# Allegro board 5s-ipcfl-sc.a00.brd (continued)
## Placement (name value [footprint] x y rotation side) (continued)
NOREF#25  -  [unnamed#2]  32.33 16.79 0 top
NOREF#26  -  []  60.38 238.12 0 top
NOREF#27  -  []  239.42 114.25 0 top
NOREF#28  -  []  112.34 232.56 0 top
NOREF#29  -  []  27.81 225.63 90 top
NOREF#30  -  []  7.34 241.53 0 top
NOREF#31  -  []  40.71 51.48 0 top
NOREF#32  -  []  31.98 208.58 0 top
NOREF#33  -  []  241.99 175.21 90 top
NOREF#34  -  []  62.43 110.49 0 top
NOREF#35  -  []  22.07 96.17 90 top
NOREF#36  -  []  206.78 1.97 0 top
NOREF#37  -  [unnamed#2]  17.88 237.82 0 top
NOREF#38  -  []  241.4 210.33 90 top
NOREF#39  -  []  109.69 88.81 0 top
NOREF#40  -  []  101.56 88.81 0 top
NOREF#41  -  []  241 46.07 90 top
NOREF#42  -  []  83.02 88.81 0 top
NOREF#43  -  []  37.62 56.97 0 top
NOREF#44  -  []  6.48 119.45 0 top
NOREF#45  -  []  48.08 5.31 0 top
NOREF#46  -  []  158.57 89 0 top
NOREF#47  -  []  149.2 14.69 0 top
NOREF#48  -  []  96.22 39.9 0 top
NOREF#49  -  []  129.3 53.59 0 top
NOREF#50  -  []  129.95 230.68 0 top
NOREF#51  -  []  138.35 32.37 0 top
NOREF#52  -  [unnamed#2]  229.49 25.76 0 top
NOREF#53  -  []  16.77 155.88 0 top
NOREF#54  -  []  14.7 232.64 90 top
NOREF#55  -  []  194.73 239.53 0 top
NOREF#56  -  []  125.09 2.29 0 top
NOREF#57  -  []  80.42 13.59 0 top
NOREF#58  -  []  109.54 104.73 0 top
NOREF#59  -  []  123.85 44.65 0 top
NOREF#60  -  []  47.37 -43.4 0 top
NOREF#61  -  []  38.2 78.61 0 top
NOREF#62  -  []  146.81 2.16 0 top
NOREF#63  -  []  106.77 89.45 0 top
NOREF#64  -  []  241.27 10.77 90 top
NOREF#65  -  []  38.23 128.02 0 top
NOREF#66  -  []  165.89 210.38 0 top
NOREF#67  -  []  90.6 88.75 0 top
NOREF#68  -  []  36.6 13.84 0 top
NOREF#69  -  []  160.88 4.92 0 top
NOREF#70  -  [unnamed#2]  24.28 235.13 180 bottom
NOREF#71  -  [unnamed#2]  215.01 10.03 180 bottom
NOREF#72  -  [unnamed#2]  227.33 237.97 180 bottom
O2C1  2200PF/50V  [MX_C0402_SMALL_T01]  226.44 29.44 180 top
O2C2  100PF/50V  [MX_C0402_SMALL_T01]  66.98 71.17 0 top
O2C4  100PF/50V  [MX_C0402_SMALL_T01]  227.74 74.83 180 top
O2C5  2200PF/50V  [MX_C0402_SMALL_T01]  225.65 28.32 0 top
O2CB1  0.1UF/6.3V  [MX_C0201]  204.22 29.64 180 top
O2CB2  0.1UF/16V  [MX_C0402_SMALL_T01]  225.3 22.1 270 top
O2CB3  0.1UF/6.3V  [MX_C0201]  222.61 42.04 0 top
O2CB4  0.1UF/6.3V  [MX_C0201]  224.87 31.37 90 top
O2CB5  0.1UF/6.3V  [MX_C0201]  225.48 37.05 0 top
O2CB6  0.1UF/6.3V  [MX_C0201]  225.48 37.97 0 top
O2CB7  0.1UF/16V  [MX_C0402_SMALL_T01]  217.93 22.1 270 top
O2CB8  0.1UF/16V  [MX_C0402_SMALL_T01]  207.8 22.05 270 top
O2CB10  0.1UF/16V  [MX_C0402_SMALL_T01]  220.24 21.97 270 top
O2CB11  0.1UF/16V  [MX_C0402_SMALL_T01]  219.33 22.1 270 top
O2CB12  470PF/50V  [MX_C0402_SMALL_T01]  204.19 27.79 180 top
O2CB15  0.1UF/16V  [MX_C0402_SMALL_T01]  226.31 24.37 0 top
O2CB16  0.1UF/16V  [MX_C0402_SMALL_T01]  224.38 22.1 270 top
O2CB17  0.1UF/6.3V  [MX_C0201]  216.92 43.31 90 top
O2CB19  0.1UF/6.3V  [MX_C0201]  227.33 32.59 270 top
O2CB20  0.1UF/6.3V  [MX_C0201]  225.78 31.37 90 top
O2Q6  MBT3904DW1T1G  [MX_SOT363_PHILIPS]  219.58 46.1 90 top
O2R1  43.2  [MX_R0402_SMALL_T01]  222.07 21.97 90 top
O2R2  3K  [MX_R0402_SMALL_T01]  228.24 32.59 270 top
O2R3  8.2K  [MX_R0402_SMALL_T01]  216.81 48.06 180 top
O2R5  10K  [MX_R0402_SMALL_T01]  225.54 36.12 180 top
O2R8  680  [MX_R0402_SMALL_T01]  218.44 48.06 0 top
O2R10  330K  [MX_R0402_SMALL_T01]  226.31 23.44 180 top
O2R11  30K  [MX_R0402_SMALL_T01]  220.34 47.88 0 top
O2R20  10K  [MX_R0402_SMALL_T01]  217.86 43.31 270 top
O2R21  30K  [MX_R0402_SMALL_T01]  206.25 45.85 270 top
O2R22  2.74K  [MX_R0402_SMALL_T01]  228.75 33.86 180 top
O3R5  33  [MX_R0402_SMALL_T01]  59.87 10.64 0 top
OR3  1K  [MX_R0402_SMALL_T01]  223.44 21.97 90 top
OR5  20K  [MX_R0402_SMALL_T01]  215.26 19.51 180 top
OR6  8.45K  [TX_R0402]  215.26 20.42 180 top
OR22  10K  [MX_R0402_SMALL_T01]  204.22 30.94 180 top
OR29  10K  [MX_R0402_SMALL_T01]  202.51 25.12 0 top
OR34  1K  [MX_R0402_SMALL_T01]  204.22 26.87 0 top
OR35  10K  [MX_R0402_SMALL_T01]  204.2 34.39 180 top
OR37  10K  [MX_R0402_SMALL_T01]  216.81 45.55 90 top
OR44  10K  [MX_R0402_SMALL_T01]  204.17 25.96 180 top
OR51  10K  [MX_R0402_SMALL_T01]  207.8 53.75 180 top
OR52  1K  [MX_R0402_SMALL_T01]  207.77 49.15 90 top
OR53  10K  [MX_R0402_SMALL_T01]  212.29 43.31 90 top
OR56  10K  [MX_R0402_SMALL_T01]  220.62 43.29 270 top
OR57  10K  [MX_R0402_SMALL_T01]  218.8 43.29 270 top
OR59  10K  [MX_R0402_SMALL_T01]  227.15 35.23 180 top
OR60  0  [MX_R0402_SMALL_T01]  213.23 43.31 270 top
OR61  0  [MX_R0402_SMALL_T01]  215.06 43.31 270 top
OR65  1K  [MX_R0402_SMALL_T01]  207.77 47.5 270 top
OR68  8.2K  [MX_R0402_SMALL_T01]  213.16 49.43 90 top
OR69  8.2K  [MX_R0402_SMALL_T01]  211.81 49 180 top
OR70  10K  [MX_R0402_SMALL_T01]  204.7 7.37 0 top
P1C2  470PF/50V  [MX_C0402_SMALL_T01]  235.08 148.21 180 top
P1CB1  0.1UF/16V  [MX_C0402_SMALL_T01]  229.87 194.18 180 top
P1CB2  0.1UF/6.3V  [MX_C0201]  229.34 186.31 270 top
P1CB3  0.1UF/6.3V  [MX_C0201]  229.87 201.04 180 top
P1CB4  0.1UF/6.3V  [MX_C0201]  229.67 151.23 180 top
P1CB5  1UF/6.3V  [MX_C0402_SMALL_T01]  230.2 163.09 90 top
P1CB8  0.1UF/16V  [MX_C0402_SMALL_T01]  229.67 150.32 180 top
P1CB10  1000PF/50V  [MX_C0402_SMALL_T01]  62.74 218.95 0 top
P1CB11  1000PF/50V  [MX_C0402_SMALL_T01]  62.74 219.96 0 top
P1CB12  0.1UF/16V  [MX_C0402_SMALL_T01]  230.2 166.24 270 top
P1CB13  10UF/25V  [MX_C1206_H75]  49.86 201.5 0 top
P1CB14  10UF/25V  [MX_C1206_H75]  51.18 163.47 0 top
P1CB15  10UF/25V  [MX_C1206_H75]  51.18 160.93 0 top
P1CB16  10UF/25V  [MX_C1206_H75]  49.94 182.68 0 top
P1CB17  10PF/50V  [MX_C0402_SMALL_T01]  62.74 217.98 0 top
P1R1  8.2K  [MX_R0402_SMALL_T01]  230.25 168.28 90 top
P1R2  49.9  [MX_R0402_SMALL_T01]  235.08 146.18 180 top
P1R3  20K  [MX_R0402_SMALL_T01]  235.08 147.19 0 top
P1R4  100  [MX_R0402_SMALL_T01]  230.25 169.93 270 top
P3  POWER_CON_2X2P  [MX_PWR_2X2P_165_HD_LF3]  59.31 227.46 270 top
P7  AC_1205G  [MX_BUZZ_256_BD472_H394_LF3]  29.84 49.68 90 top
P17  HEADER_1X3P  [MX_HD_1X3P_100_LF3]  206.71 5.28 180 top
P23  HEADER_2X5P_K8  [MX_HD_2X5P_100_K8_LF3]  32.89 4.32 180 top
P24  BOX_HD_2X10P  [MX_BOX_HD_2X10P_79_K20_LF3]  238.12 101.09 270 top
P29  WAFER_HD_1X4P  [MX_WF_HD_1X4P_1H_LF3]  238.27 222.07 270 top
P61  SATA_CON_7P  [MX_SATA_CON_7P_50_2HD_LF3]  236.73 63.63 90 top
P62  SATA_CON_7P  [MX_SATA_CON_7P_50_2HD_LF3]  236.73 45.85 90 top
P63  SATA_CON_7P  [MX_SATA_CON_7P_50_2HD_LF3]  236.73 28.07 90 top
P64  SATA_CON_7P  [MX_SATA_CON_7P_50_2HD_LF3]  236.73 10.29 90 top
P70  WAFER_HD_4P  [MX_WF_HD_1X4P_100_HD_LF3]  151.26 238.38 0 top
P118  FPC_CON_12P  [MX_FPC_12P_20_2HD_ACES_B]  195.45 6.35 0 top
P150  BOX_HEAD_2X10P  [MX_BOX_HD_2X10P_79_K20_LF5]  238.12 127.15 270 top
P189  WAFER_HD_1X12P  [MX_WAFER_HD_1X12P_79_HD_LF5]  66.49 5.82 180 top
P215  HEADER_1X2P  [MX_HD_1X2P_100_LF3]  121.03 4.83 180 top
P216  HEADER_1X2P  [MX_HD_1X2P_100_LF3]  127.33 4.84 180 top
P217  HEADER_1X3P  [MX_HD_1X3P_100_LF3]  135 4.83 180 top
P311  HEADER_1X5P  [HD_1X5P_100_JVE_LF3]  146.65 4.83 180 top
P312  HEADER_1X4P  [HD_1X4P_79_LF3]  148.73 8.74 180 top
P458  WAFER_HD_4P  [MX_WF_HD_1X4P_100_HD_LF3]  132.97 238.38 0 top
P461  WAFER_HD_1X4P  [MX_WF_HD_1X4P_1H_LF3]  120.78 238.38 0 top
P_HDDFAN  WTOB_CON_4P  [MX_WTOB_4P_49_2H_XINA]  88.6 7.29 0 top
PC1  22UF/6.3V  [MX_C0603_SMALL_T02]  124.46 160.53 90 bottom
PC2  22UF/6.3V  [MX_C0603_SMALL_T02]  121.41 160.55 90 bottom
PC3  22UF/6.3V  [MX_C0603_SMALL_T02]  119.71 156.82 270 bottom
PC4  22UF/6.3V  [MX_C0603_SMALL_T02]  120.14 166.88 0 top
PC5  22UF/6.3V  [MX_C0603_SMALL_T02]  126.75 160.53 90 bottom
PC6  22UF/6.3V  [MX_C0603_SMALL_T02]  121.03 156.82 270 bottom
PC7  22UF/6.3V  [MX_C0603_SMALL_T02]  125.46 168.3 0 bottom
PC8  22UF/6.3V  [MX_C0603_SMALL_T02]  125.46 169.67 0 bottom
PC9  22UF/6.3V  [MX_C0603_SMALL_T02]  122.8 171.07 180 bottom
PC10  22UF/6.3V  [MX_C0603_SMALL_T02]  122.83 166.95 180 top
PC11  22UF/6.3V  [MX_C0603_SMALL_T02]  125.46 171.07 0 bottom
PC12  22UF/6.3V  [MX_C0603_SMALL_T02]  122.8 169.67 180 bottom
PC13  0.1UF/6.3V  [MX_C0201]  55.32 121.67 270 top
PC15  2.2UF/6.3V  [MX_C0603_SMALL_T01]  123.32 97.28 180 top
PC118  10UF/16V  [MX_C0805_SMALL_T02]  210.69 128.4 180 top
PC121  1000PF/50V  [MX_C0402_SMALL_T01]  52.27 123.7 180 top
PC122  22PF/50V  [MX_C0402_SMALL_T01]  213.23 128.55 0 top
PC126  330PF/50V  [MX_C0402_SMALL_T01]  214.45 124.84 0 top
PC131  1UF/25V  [MX_C0603_SMALL_T01]  214.04 133.13 0 top
PC132  1UF/25V  [MX_C0603_SMALL_T01]  238.9 211.48 180 top
PC133  1000PF/50V  [MX_C0402_SMALL_T01]  135.86 109.52 270 top
PC137  10UF/25V  [MX_C1206_H75]  66.14 129.06 90 top
PC138  10UF/25V  [MX_C1206_H75]  65.99 134.11 270 top
PC142  22UF/6.3V  [MX_C0603_SMALL_T02]  79.04 135.61 90 top
PC149  22UF/6.3V  [MX_C0603_SMALL_T02]  128.19 151.89 0 top
PC150  10UF/6.3V  [MX_C0603_SMALL_T01]  133.99 101.6 270 top
PC151  1UF/25V  [MX_C0603_SMALL_T01]  128.52 98.93 180 top
PC152  1000PF/50V  [MX_C0402_SMALL_T01]  135.1 96.01 90 top
PC153  0.022UF/16V  [MX_C0402_SMALL_T01]  125.09 103.12 270 top
PC154  0.033U/16V  [MX_C0402_SMALL_T01]  129.92 95.63 0 top
PC155  470PF/50V  [MX_C0402_SMALL_T01]  131.32 98.93 0 top
PC156  22UF/6.3V  [MX_C0603_SMALL_T02]  122.81 100.84 270 top
PC157  22UF/6.3V  [MX_C0603_SMALL_T02]  121.41 100.84 270 top
PC158  0.01UF/50V  [MX_C0402_SMALL_T01]  131.83 97.66 90 top
PC159  2200PF/50V  [MX_C0402_SMALL_T01]  131.7 100.33 270 top
PC160  4700PF/50V  [MX_C0402_SMALL_T01]  125.12 99.31 270 top
PC161  22UF/6.3V  [MX_C0603_SMALL_T02]  126.11 108.41 0 top
PC162  22UF/6.3V  [MX_C0603_SMALL_T02]  126.11 109.73 0 top
PC163  22UF/6.3V  [MX_C0603_SMALL_T02]  121.41 152.4 90 top
PC164  22UF/6.3V  [MX_C0603_SMALL_T02]  122.81 152.4 90 top
PC193  22UF/6.3V  [MX_C0603_SMALL_T02]  210.03 112.34 180 top
PC194  22UF/6.3V  [MX_C0603_SMALL_T02]  214.17 111.89 270 top
PC205  10UF/25V  [MX_C1206]  201.93 94.79 0 top
PC206  10UF/25V  [MX_C1206]  201.93 92.35 0 top
PC207  10UF/16V  [MX_C0805_SMALL_T02]  200.79 90.17 180 top
PC208  0.1UF/25V  [MX_C0603_SMALL_T01]  220.5 111.56 0 top
PC209  1000PF/50V  [MX_C0402_SMALL_T01]  189.43 91.47 180 top
PC210  0.1UF/25V  [MX_C0603_SMALL_T01]  195.91 92.02 90 top
PC211  1000PF/50V  [MX_C0402_SMALL_T01]  206.45 89.33 270 top
PC212  1UF/25V  [MX_C0603_SMALL_T01]  195.71 90.17 0 top
PC213  10UF/6.3V  [MX_C0603_SMALL_T01]  202.49 65.3 0 top
PC214  680PF/50V  [MX_C0603]  207.14 86.61 270 top
PC215  1000PF/50V  [MX_C0402_SMALL_T01]  202.44 82.55 0 top
PC217  56PF/50V  [MX_C0402_SMALL_T01]  189.18 89.64 0 top
PC218  0.1UF/25V  [MX_C0603_SMALL_T01]  187.43 90.81 90 top
PC231  0.1UF/6.3V  [MX_C0201]  230.17 160.53 270 top
PC232  1UF/25V  [MX_C0603_SMALL_T01]  227.97 165.61 0 top
PC233  1UF/25V  [MX_C0603_SMALL_T01]  228.35 190.25 180 top
PC234  0.1UF/6.3V  [MX_C0201]  226.19 195.58 180 top
PC236  1UF/25V  [MX_C0603_SMALL_T01]  226.06 190.25 180 top
PC238  0.1UF/6.3V  [MX_C0201]  230.25 186.31 270 top
PC239  22UF/6.3V  [MX_C0603_SMALL_T02]  224.92 165.61 180 top
PC240  22UF/6.3V  [MX_C0603_SMALL_T02]  224.92 164.21 180 top
PC241  0.1UF/16V  [MX_C0402_SMALL_T01]  229.74 184.53 0 top
PC242  1000PF/50V  [MX_C0402_SMALL_T01]  234.19 203.48 270 top
PC243  10UF/16V  [MX_C0805_SMALL_T02]  236.91 205.71 180 top
PC247  10PF/50V  [MX_C0402_SMALL_T01]  228.09 163.58 0 top
PC272  22UF/6.3V  [MX_C0603_SMALL_T02]  129.84 116.56 90 top
PC273  22UF/6.3V  [MX_C0603_SMALL_T02]  131.47 113.8 90 top
PC274  1UF/25V  [MX_C0603_SMALL_T01]  123.67 116.94 180 top
PC329  22UF/6.3V  [MX_C0603_SMALL_T02]  124.66 153.29 180 top
PC331  22UF/6.3V  [MX_C0603_SMALL_T02]  124.66 151.89 180 top
PC332  22UF/6.3V  [MX_C0603_SMALL_T02]  124.69 154.58 180 bottom
PC333  22UF/6.3V  [MX_C0603_SMALL_T02]  124.69 155.98 180 bottom
PC334  22UF/6.3V  [MX_C0603_SMALL_T02]  128.27 155.32 0 bottom
PC335  22UF/6.3V  [MX_C0603_SMALL_T02]  128.19 152.91 0 bottom
PC339  1000PF/50V  [MX_C0402_SMALL_T01]  217.67 145.34 180 top
PC341  10UF/16V  [MX_C0805_SMALL_T02]  217.68 136.12 180 top
PC343  1800PF/50V  [MX_C0402_SMALL_T01]  205.1 85.09 180 top
PC481  22UF/6.3V  [MX_C0603_SMALL_T02]  190.8 164.01 270 top
PC483  10UF/6.3V  [MX_C0603_SMALL]  212.85 156.16 0 top
PC484  1UF/6.3V  [MX_C0402_SMALL_T01]  207.82 145.19 180 top
PC485  1000PF/50V  [MX_C0402_SMALL_T01]  209.14 155.07 90 top
PC486  0.1UF/16V  [MX_C0402_SMALL_T01]  218.29 157.58 90 top
PC566  1000PF/50V  [MX_C0402_SMALL_T01]  120.02 56.13 90 top
PC567  1000PF/50V  [MX_C0402_SMALL_T01]  115.23 53.08 180 top
PC568  2.2UF/6.3V  [MX_C0603_SMALL_T01]  116.28 49.66 180 top
PC569  0.1UF/6.3V  [MX_C0201]  116.31 56.13 90 top
PC570  0.1UF/6.3V  [MX_C0201]  117.25 56.13 90 top
PC601  680PF/50V  [MX_C0402_SMALL_T01]  65.75 165.48 90 top
PC602  1000PF/50V  [MX_C0402_SMALL_T01]  65.61 154.28 180 top
PC603  1000PF/50V  [MX_C0402_SMALL_T01]  63.92 165.48 270 top
PC604  1000PF/50V  [MX_C0402_SMALL_T01]  64.85 155.97 270 top
PC605  1000PF/50V  [MX_C0402_SMALL_T01]  59.05 155.96 270 top
PC606  22UF/6.3V  [MX_C0603_SMALL_T02]  73.86 156.08 180 top
PC607  0.1UF/25V  [MX_C0603_SMALL_T01]  71.25 166.24 180 top
PC608  1UF/25V  [MX_C0603_SMALL_T01]  68.33 169.95 270 top
PC609  680PF/50V  [MX_C0402_SMALL_T01]  65.71 147.68 90 top
PC610  1000PF/50V  [MX_C0402_SMALL_T01]  65.89 136.93 180 top
PC611  1000PF/50V  [MX_C0402_SMALL_T01]  63.88 147.68 270 top
PC612  1000PF/50V  [MX_C0402_SMALL_T01]  59.05 138.28 270 top
PC613  1000PF/50V  [MX_C0402_SMALL_T01]  64.67 138.29 270 top
PC614  22UF/6.3V  [MX_C0603_SMALL_T02]  78.74 140.34 270 top
PC615  0.1UF/25V  [MX_C0603_SMALL_T01]  72.19 149.53 180 top
PC616  1UF/25V  [MX_C0603_SMALL_T01]  68.83 152.3 270 top
PC617  10UF/25V  [MX_C1206_H75]  51.18 153.62 0 top
PC618  10UF/25V  [MX_C1206_H75]  51.18 156.06 0 top
PC619  10UF/25V  [MX_C1206_H75]  50.62 170.54 0 top
PC620  10UF/25V  [MX_C1206_H75]  50.62 168.07 0 top
PC642  1UF/6.3V  [MX_C0402_SMALL_T01]  46.15 237.06 90 top
PC661  1NF/25V  [MX_C0402_SMALL_T01]  213.36 132.05 180 top
PC832  22UF/6.3V  [MX_C0603_SMALL_T02]  210.03 111 180 top
PC834  22UF/6.3V  [MX_C0603_SMALL_T02]  131.19 165.1 90 top
PC5801  0.1UF/6.3V  [MX_C0201]  72.64 209.3 270 top
PC5802  0.47UF/16V  [MX_C0603_SMALL_T01]  73.28 211.71 180 top
PC5803  0.47UF/16V  [MX_C0603_SMALL_T01]  75.31 211.63 270 top
PC5804  0.1UF/6.3V  [MX_C0201]  76.07 208.66 270 top
PC5805  0.47UF/16V  [MX_C0603_SMALL_T01]  72.97 214.83 180 top
PC5806  0.1UF/6.3V  [MX_C0201]  70.82 213.49 180 top
PC5807  0.47UF/16V  [MX_C0603_SMALL_T01]  76.9 225.68 90 top
PC5808  0.1UF/6.3V  [MX_C0201]  75.9 228.73 90 top
PC5809  0.47UF/16V  [MX_C0603_SMALL_T01]  78.27 225.68 90 top
PC5810  0.1UF/6.3V  [MX_C0201]  78.64 228.73 90 top
PC5811  0.47UF/16V  [MX_C0603_SMALL_T01]  78.36 211.68 270 top
PC5812  0.1UF/6.3V  [MX_C0201]  77.11 208.71 270 top
PC5813  0.1UF/16V  [MX_C0402_SMALL_T01]  73.15 218.44 180 top
PC5814  0.1UF/6.3V  [MX_C0201]  90.4 222.38 0 top
PC5815  1000PF/50V  [MX_C0402_SMALL_T01]  82.93 211.33 270 top
PC5816  82PF/50V  [MX_C0402_SMALL_T01]  80.52 213.36 0 top
PC5817  0.1UF/16V  [MX_C0402_SMALL_T01]  81.84 209.42 270 top
PC5818  270PF/50V  [MX_C0402_SMALL_T01]  80.01 209.42 90 top
PC5819  1000PF/50V  [MX_C0402_SMALL_T01]  82.55 212.85 0 top
PC5820  1000PF/50V  [MX_C0402_SMALL_T01]  83.12 226.06 90 top
PC5821  390PF/50V  [MX_C0402_SMALL_T01]  80.01 228.35 270 top
PC5822  0.1UF/16V  [MX_C0402_SMALL_T01]  81.92 228.78 90 top
PC5823  82PF/50V  [MX_C0402_SMALL_T01]  80.64 224.79 0 top
PC5824  1000PF/50V  [MX_C0402_SMALL_T01]  82.3 224.79 0 top
PC5825  0.1UF/16V  [MX_C0402_SMALL_T01]  70.94 217.17 0 top
PC5826  0.1UF/16V  [MX_C0402_SMALL_T01]  72.77 227.08 270 top
PC5827  0.47UF/25V  [MX_C0603_SMALL_T01]  88.85 220.07 0 top
PC5828  1000PF/50V  [MX_C0402_SMALL_T01]  86.36 225.58 0 top
PC5829  1UF/25V  [MX_C0603_SMALL_T01]  84.71 225.3 90 top
PC5830  0.1UF/16V  [MX_C0402_SMALL_T01]  72.77 221.74 180 top
PC5901  0.1UF/25V  [MX_C0603_SMALL_T01]  71.63 183.67 180 top
PC5902  1000PF/50V  [MX_C0402_SMALL_T01]  63.86 182.96 270 top
PC5903  1UF/25V  [MX_C0603_SMALL_T01]  69.09 188.95 180 top
PC5904  22UF/6.3V  [MX_C0603_SMALL_T02]  73.91 173.69 180 top
PC5905  680PF/50V  [MX_C0402_SMALL_T01]  65.68 182.96 90 top
PC5906  1000PF/50V  [MX_C0402_SMALL_T01]  65.53 171.96 180 top
PC5907  1000PF/50V  [MX_C0402_SMALL_T01]  59.05 173.48 270 top
PC5908  1000PF/50V  [MX_C0402_SMALL_T01]  64.77 173.53 270 top
PC5909  680PF/50V  [MX_C0402_SMALL_T01]  65.66 200.53 90 top
PC5910  1000PF/50V  [MX_C0402_SMALL_T01]  65.56 189.43 180 top
PC5911  1000PF/50V  [MX_C0402_SMALL_T01]  63.83 200.53 270 top
PC5912  1000PF/50V  [MX_C0402_SMALL_T01]  59.44 191.13 270 top
PC5913  1000PF/50V  [MX_C0402_SMALL_T01]  65.66 191.13 270 top
PC5914  22UF/6.3V  [MX_C0603_SMALL_T02]  74.68 191.16 180 top
PC5915  0.1UF/25V  [MX_C0603_SMALL_T01]  67.31 202.06 180 top
PC5916  1UF/25V  [MX_C0603_SMALL_T01]  64.52 206.12 180 top
PC5917  10UF/25V  [MX_C1206_H75]  49.94 186.66 0 top
PC5918  10UF/25V  [MX_C1206_H75]  49.94 189.1 0 top
PC5919  10UF/25V  [MX_C1206_H75]  49.83 194.94 0 top
PC5920  10UF/25V  [MX_C1206_H75]  49.83 197.38 0 top
PC6101  680PF/50V  [MX_C0402_SMALL_T01]  113.92 224.41 90 top
PC6102  1000PF/50V  [MX_C0402_SMALL_T01]  115.06 224.41 90 top
PC6103  1000PF/50V  [MX_C0402_SMALL_T01]  120.14 218.41 180 top
PC6104  1000PF/50V  [MX_C0402_SMALL_T01]  108.33 227.46 90 top
PC6105  1000PF/50V  [MX_C0402_SMALL_T01]  103.38 227.08 0 top
PC6106  22UF/6.3V  [MX_C0603_SMALL_T02]  108.71 201.55 180 top
PC6107  0.1UF/25V  [MX_C0603_SMALL_T01]  98.55 228.73 270 top
PC6108  1UF/25V  [MX_C0603_SMALL_T01]  92.66 226.59 180 top
PC6109  680PF/50V  [MX_C0402_SMALL_T01]  135.13 224.28 90 top
PC6110  1000PF/50V  [MX_C0402_SMALL_T01]  136.19 224.28 90 top
PC6111  1000PF/50V  [MX_C0402_SMALL_T01]  141.6 218.44 180 top
PC6112  1000PF/50V  [MX_C0402_SMALL_T01]  123.95 227.08 0 top
PC6113  1000PF/50V  [MX_C0402_SMALL_T01]  129.79 227.46 90 top
PC6114  22UF/6.3V  [MX_C0603_SMALL_T02]  123.44 201.55 180 top
PC6115  0.1UF/25V  [MX_C0603_SMALL_T01]  149.48 226.42 180 top
PC6116  1UF/25V  [MX_C0603_SMALL_T01]  144.63 228.68 180 top
PC6117  10UF/25V  [MX_C1206_H75]  114.53 227.66 90 top
PC6118  10UF/25V  [MX_C1206_H75]  119.15 233.93 180 top
PC6119  10UF/25V  [MX_C1206_H75]  140.39 232.11 270 top
PC6120  10UF/25V  [MX_C1206_H75]  135.92 227.94 90 top
PC6201  22UF/6.3V  [MX_C0603_SMALL_T02]  125.6 161.93 270 top
PC6202  22UF/6.3V  [MX_C0603_SMALL_T02]  127 161.93 270 top
PC6203  22UF/6.3V  [MX_C0603_SMALL_T02]  125.6 159.13 90 top
PC6204  22UF/6.3V  [MX_C0603_SMALL_T02]  127 159.13 90 top
PC6205  22UF/6.3V  [MX_C0603_SMALL_T02]  125.6 165.1 90 top
PC6206  22UF/6.3V  [MX_C0603_SMALL_T02]  129.79 165.1 90 top
PC6207  22UF/6.3V  [MX_C0603_SMALL_T02]  120.14 168.28 0 top
PC6208  22UF/6.3V  [MX_C0603_SMALL_T02]  121.41 159.13 90 top
PC6209  22UF/6.3V  [MX_C0603_SMALL_T02]  122.81 165.1 90 top
PC6210  22UF/6.3V  [MX_C0603_SMALL_T02]  124.21 159.13 90 top
PC6211  22UF/6.3V  [MX_C0603_SMALL_T02]  120.02 159.13 90 top
PC6212  22UF/6.3V  [MX_C0603_SMALL_T02]  120.02 161.93 270 top
PC6213  22UF/6.3V  [MX_C0603_SMALL_T02]  131.19 161.93 270 top
PC6214  22UF/6.3V  [MX_C0603_SMALL_T02]  122.81 156.72 270 top
PC6215  22UF/6.3V  [MX_C0603_SMALL_T02]  121.41 156.72 270 top
PC6216  22UF/6.3V  [MX_C0603_SMALL_T02]  124.21 161.93 270 top
PC6217  22UF/6.3V  [MX_C0603_SMALL_T02]  120.02 156.72 270 top
PC6218  22UF/6.3V  [MX_C0603_SMALL_T02]  124.21 165.1 90 top
PC6219  22UF/6.3V  [MX_C0603_SMALL_T02]  128.4 165.1 90 top
PC6220  22UF/6.3V  [MX_C0603_SMALL_T02]  127 165.1 90 top
PC6221  22UF/6.3V  [MX_C0603_SMALL_T02]  99.44 214.25 180 top
PC6222  22UF/6.3V  [MX_C0603_SMALL_T02]  129.21 209.4 0 top
PC6223  22UF/6.3V  [MX_C0603_SMALL_T02]  100.97 201.55 180 top
PC6224  22UF/6.3V  [MX_C0603_SMALL_T02]  123.44 200.15 180 top
PC6225  22UF/6.3V  [MX_C0603_SMALL_T02]  128.13 171.07 180 top
PC6226  22UF/6.3V  [MX_C0603_SMALL_T02]  125.46 169.67 0 top
PC6227  2.2UF/6.3V  [MX_C0603_SMALL_T01]  128.13 169.67 180 top
PC6228  22UF/6.3V  [MX_C0603_SMALL_T02]  125.46 168.28 0 top
PC6229  22UF/6.3V  [MX_C0603_SMALL_T02]  125.46 171.07 0 top
PC6230  22UF/6.3V  [MX_C0603_SMALL_T02]  122.8 168.28 180 top
PC6231  22UF/6.3V  [MX_C0603_SMALL_T02]  128.13 168.28 180 top
PC6232  22UF/6.3V  [MX_C0603_SMALL_T02]  122.8 171.07 180 top
PC6233  22UF/6.3V  [MX_C0603_SMALL_T02]  100.97 200.15 180 top
PC6234  22UF/6.3V  [MX_C0603_SMALL_T02]  108.71 200.15 180 top
PC6235  22UF/6.3V  [MX_C0603_SMALL_T02]  130.79 169.67 0 top
PC6236  22UF/6.3V  [MX_C0603_SMALL_T02]  130.79 171.07 0 top
PC6237  22UF/6.3V  [MX_C0603_SMALL_T02]  96.77 159.77 270 top
PC6238  22UF/6.3V  [MX_C0603_SMALL_T02]  96.77 165.1 270 top
PC6239  22UF/6.3V  [MX_C0603_SMALL_T02]  96.77 179.2 270 top
PC6240  22UF/6.3V  [MX_C0603_SMALL_T02]  96.77 174.37 90 top
PC6241  22UF/6.3V  [MX_C0603_SMALL_T02]  116.2 201.55 180 top
PC6242  22UF/6.3V  [MX_C0603_SMALL_T02]  116.2 200.15 180 top
PC6243  22UF/6.3V  [MX_C0603_SMALL_T02]  130.79 168.25 0 top
PC6244  22UF/6.3V  [MX_C0603_SMALL_T02]  122.8 169.67 180 top
PC6501  10UF/25V  [MX_C1206_H75]  210.87 205.74 0 top
PC6502  10UF/25V  [MX_C1206_H75]  210.87 203.17 0 top
PC6521  22UF/6.3V  [MX_C0603_SMALL_T02]  212.57 160.73 270 top
PC6522  22UF/6.3V  [MX_C0603_SMALL_T02]  212.9 154.66 0 top
PC6523  22UF/6.3V  [MX_C0603_SMALL_T02]  171.07 183.77 135 top
PC6524  22UF/6.3V  [MX_C0603_SMALL_T02]  211.54 172.16 90 top
PC6525  22UF/6.3V  [MX_C0603_SMALL_T02]  207.52 179.07 0 top
PC6526  0.1UF/25V  [MX_C0603_SMALL_T01]  228.45 206.55 270 top
PC6527  0.1UF/25V  [MX_C0603_SMALL_T01]  219.07 227.33 90 top
PC6805  10UF/6.3V  [MX_C0603_SMALL_T01]  43.26 237.85 90 top
PC6807  10UF/6.3V  [MX_C0603_SMALL_T01]  41.91 227.2 270 top
PC6808  10UF/6.3V  [MX_C0603_SMALL_T01]  43.18 227.2 270 top
PC6809  1000PF/50V  [MX_C0402_SMALL_T01]  44.78 227.89 0 top
PC6810  1UF/6.3V  [MX_C0402_SMALL_T01]  41.71 236.65 180 top
PC640625  22UF/6.3V  [MX_C0603_SMALL_T02]  120.14 169.67 0 top
PC640626  22UF/6.3V  [MX_C0603_SMALL_T02]  129.79 159.13 90 top
PC640627  22UF/6.3V  [MX_C0603_SMALL_T02]  129.79 161.93 270 top
PC640628  22UF/6.3V  [MX_C0603_SMALL_T02]  131.19 159.13 90 top
PC640629  22UF/6.3V  [MX_C0603_SMALL_T02]  121.41 161.93 270 top
PC640630  22UF/6.3V  [MX_C0603_SMALL_T02]  96.77 169.93 90 top
PC640631  100uF/16V  [MX_CE_100U_16V_5X11_LFH]  226.44 169.42 270 top
PC640632  22UF/6.3V  [MX_C0603_SMALL_T02]  124.66 156.08 180 top
PC640633  22UF/6.3V  [MX_C0603_SMALL_T02]  124.66 154.69 180 top
PC640634  22UF/6.3V  [MX_C0603_SMALL_T02]  128.27 156.08 0 top
PC640635  22UF/6.3V  [MX_C0603_SMALL_T02]  128.27 154.69 0 top
PC640636  22UF/6.3V  [MX_C0603_SMALL_T02]  128.19 153.29 0 top
PC640637  2200PF/50V  [MX_C0402_SMALL_T01]  66.42 119.51 270 top
PC640639  1000PF/50V  [MX_C0402_SMALL_T01]  76.07 137.31 180 top
PC640641  1000PF/50V  [MX_C0402_SMALL_T01]  70.48 129.74 90 top
PC640644  1000PF/50V  [MX_C0402_SMALL_T01]  66.42 121.16 90 top
PC640645  1000PF/50V  [MX_C0402_SMALL_T01]  68.76 135.36 90 top
PC640646  680PF/50V  [MX_C0402_SMALL_T01]  73.28 135.89 90 top
PC640647  0.1UF/25V  [MX_C0603_SMALL_T01]  73.28 121.41 0 top
PC640648  100PF/50V  [MX_C0402_SMALL_T01]  66.67 125.48 90 top
PC640649  4.7UF/25V  [MX_C0805_SMALL_T02]  70.31 124.56 180 top
PC640651  1000PF/50V  [MX_C0402_SMALL_T01]  76.07 138.23 180 top
PC640653  2200PF/50V  [MX_C0402_SMALL_T01]  212.09 224.03 180 top
PC640656  1000PF/50V  [MX_C0402_SMALL_T01]  210.69 193.57 90 top
PC640658  1000PF/50V  [MX_C0402_SMALL_T01]  219.68 198.32 180 top
PC640660  1000PF/50V  [MX_C0402_SMALL_T01]  209.22 198.11 0 top
PC640661  1000PF/50V  [MX_C0402_SMALL_T01]  213.59 224.41 90 top
PC640662  680PF/50V  [MX_C0402_SMALL_T01]  219.41 187.55 90 top
PC640663  0.1UF/25V  [MX_C0603_SMALL_T01]  213.23 216.19 270 top
PC640664  100PF/50V  [MX_C0402_SMALL_T01]  217.3 223.9 0 top
PC640665  4.7UF/6.3V  [MX_C0603_SMALL_T01]  216.28 217.81 270 top
PC640667  1000PF/50V  [MX_C0402_SMALL_T01]  210.69 187.9 90 top
PC640671  0.1UF/25V  [MX_C0603_SMALL_T01]  215.65 224.54 90 top
PC640672  0.1UF/16V  [MX_C0402_SMALL_T01]  65.81 123.04 0 top
PC640674  0.1UF/25V  [MX_C0603_SMALL_T01]  62.74 125.35 90 top
PC640675  1000PF/50V  [MX_C0402_SMALL_T01]  39.5 230.89 90 top
PC640676  10UF/16V  [MX_C0805_SMALL_T02]  35.94 228.22 90 top
PC640679  1UF/25V  [MX_C0603_SMALL_T01]  53.75 125.68 180 top
PC640681  0.1UF/6.3V  [MX_C0201]  51.31 131.01 180 top
PC640682  1UF/25V  [MX_C0603_SMALL_T01]  19.18 152.02 180 top
PC640683  10PF/50V  [MX_C0402_SMALL_T01]  55.85 201.98 270 top
PC640684  10PF/50V  [MX_C0402_SMALL_T01]  71.04 189.1 0 top
PC640685  10PF/50V  [MX_C0402_SMALL_T01]  66.04 207.7 90 top
PC640686  10PF/50V  [MX_C0402_SMALL_T01]  55.91 154.33 90 top
PC640687  10PF/50V  [MX_C0402_SMALL_T01]  69.98 171.32 0 top
PC640688  10PF/50V  [MX_C0402_SMALL_T01]  68.83 153.9 180 top
PC640689  10PF/50V  [MX_C0402_SMALL_T01]  74.47 189.97 180 top
PC640690  10PF/50V  [MX_C0402_SMALL_T01]  74.17 172.31 180 top
PC640691  10PF/50V  [MX_C0402_SMALL_T01]  80.09 140.41 270 top
PC640692  10PF/50V  [MX_C0402_SMALL_T01]  74.07 154.94 180 top
PCE11  270UF/16V  [MX_CE_138_BD335_H512_37_LFH]  48.82 146.2 0 top
PCE12  820UF/2.5V  [MX_CE_98_BD268_H374_37_LFH]  83.9 137.87 270 top
PCE13  820UF/2.5V  [MX_CE_98_BD268_H374_37_LFH]  92.08 145.03 270 top
PCE14  820UF/2.5V  [MX_CE_98_BD268_H374_37_LFH]  121.56 106.38 0 top
PCE17  560UF/6.3V  [MX_CE_98_BD268_H374_37_LFH]  210.13 99.06 270 top
PCE18  820UF/2.5V  [MX_CE_98_BD268_H374_37_LFH]  196.85 74.3 0 top
PCE23  270UF/16V  [MX_CE_138_BD335_H512_37_LFH]  43.29 71.12 0 top
PCE591  270UF/16V  [MX_CE_138_BD335_H512_37_LFH]  52.7 217.3 0 top
PCE601  270UF/16V  [MX_CE_138_BD335_H512_37_LFH]  48.64 176.91 0 top
PCE611  270UF/16V  [MX_CE_138_BD335_H512_37_LFH]  101.98 233.55 0 top
PCE651  560UF/6.3V  [MX_CE_98_BD268_H374_37_LFH]  213.82 210.54 270 top
PCE652  820UF/2.5V  [MX_CE_98_BD268_H374_37_LFH]  218.01 162.99 270 top
PCE653  820UF/2.5V  [MX_CE_98_BD268_H374_37_LFH]  215.93 170.54 270 top
PCE6201  560UF/6.3V  [MX_CE_98_BD268_H374_37_LFH]  90.13 182.01 270 top
PCE6202  560UF/6.3V  [MX_CE_98_BD268_H374_37_LFH]  90.13 174.22 270 top
PCE6203  560UF/6.3V  [MX_CE_98_BD268_H374_37_LFH]  90.13 166.04 270 top
PCE6204  560UF/6.3V  [MX_CE_98_BD268_H374_37_LFH]  90.13 157.87 270 top
PCE6205  560UF/6.3V  [MX_CE_98_BD268_H374_37_LFH]  83.44 178.05 270 top
PCE6206  560UF/6.3V  [MX_CE_98_BD268_H374_37_LFH]  97.43 205.1 270 top
PCE6207  560UF/6.3V  [MX_CE_98_BD268_H374_37_LFH]  104.9 205.1 270 top
PCE6208  560UF/6.3V  [MX_CE_98_BD268_H374_37_LFH]  112.37 205.1 270 top
PCE6209  560UF/6.3V  [MX_CE_98_BD268_H374_37_LFH]  119.84 205.1 270 top
PCE6210  560UF/6.3V  [MX_CE_98_BD268_H374_37_LFH]  127.36 205.1 270 top
PCE6211  560UF/6.3V  [MX_CE_98_BD268_H374_37_LFH]  83.44 162.05 270 top
PCE6212  560UF/6.3V  [MX_CE_98_BD268_H374_37_LFH]  210.52 137.34 270 top
PCH  KABYLAKE_PCH  [BGA_885P_909X949_N]  170.81 50.67 180 top
PD1  SS14  [MX_SMA]  51.05 234.82 0 top
PD2  SS14  [MX_SMA]  51.05 238.25 0 top
PD3  SS14  [MX_SMA]  90.25 97.23 225 top
PJP9  -  [SHORTPIN]  70.74 160.02 0 bottom
PJP10  -  [SHORTPIN]  73.28 161.93 180 bottom
PJP11  -  [SHORTPIN]  71.07 143.51 0 bottom
PJP12  -  [SHORTPIN]  73.15 145.52 180 bottom
PJP17  -  [SHORTPIN]  83.97 135.69 270 bottom
PJP19  -  [SHORTPIN]  197.28 75.11 135 top
PJP20  -  [SHORTPIN]  225.55 168.4 0 top
PJP25  -  [SHORTPIN]  214.88 112.54 180 top
PJP591  -  [SHORTPIN]  70.92 177.8 0 bottom
PJP592  -  [SHORTPIN]  73.53 179.58 180 bottom
PJP593  -  [SHORTPIN]  70.99 195.2 0 bottom
PJP594  -  [SHORTPIN]  73.25 197.23 180 bottom
PJP595  -  [SHORTPIN]  55.96 217.32 180 bottom
PJP611  -  [SHORTPIN]  108.33 213.74 225 bottom
PJP612  -  [SHORTPIN]  104.83 214.35 45 bottom
PJP613  -  [SHORTPIN]  130.07 213.66 225 bottom
PJP614  -  [SHORTPIN]  126.47 214.45 45 bottom
PJP615  -  [SHORTPIN]  103.5 234.44 270 top
PJP621  -  [SHORTPIN]  108.2 179.6 315 bottom
PJP622  -  [SHORTPIN]  106.93 181.61 315 bottom
PJP623  -  [SHORTPIN]  112.29 180.9 315 bottom
PJP624  -  [SHORTPIN]  110.77 180.85 315 bottom
PJP652  -  [SHORTPIN]  215.16 170.09 135 top
PL1  1UH/11A  [MX_INDUCTOR_2P_287X260]  222.33 210.41 0 top
PL12  1UH/14A  [MX_INDU_D_2P_S309_MAGI_LF3]  216.31 106.45 90 top
PL13  1UH/11A  [MX_INDUCTOR_2P_287X260]  196.09 82.8 270 top
PL591  0.25uH  [MX_INDUCT_D_2P_433X315_LF3]  71.96 178.69 180 top
PL592  0.25uH  [MX_INDUCT_D_2P_433X315_LF3]  71.96 196.29 180 top
PL601  0.25uH  [MX_INDUCT_D_2P_433X315_LF3]  71.96 161.09 180 top
PL602  0.25uH  [MX_INDUCT_D_2P_433X315_LF3]  72.09 144.5 180 top
PL611  0.25uH  [MX_INDUCT_D_2P_433X315_LF3]  106.68 214.38 0 top
PL612  0.25uH  [MX_INDUCT_D_2P_433X315_LF3]  128.4 214.38 0 top
PL631  1UH/11A  [MX_INDUCTOR_2P_287X260]  76.91 130.33 0 top
PL652  0.8UH/31A  [MX_INDU_D_2P_S445_LF3]  214.6 180.21 0 top
PL661  1UH/11A  [MX_INDUCTOR_2P_287X260]  212.43 117.77 270 top
PQ2  2N7002  [MX_SOT23_H43]  65.96 215.49 270 top
PQ10  2N7002  [MX_SOT23_H43]  209.68 220.73 270 top
PQ11  UM6K1N  [MX_SOT363]  230.14 20.81 180 top
PQ19  BSC889N03LS  [MX_SO_8FL_COLAY_9VI]  129.51 104.6 270 top
PQ23  2N7002  [MX_SOT23_H43]  52.7 121.64 0 top
PQ28  PMPB20EN  [MX_SOT1220_NXP]  68.71 130.3 0 top
PQ29  PMPB20EN  [MX_SOT1220_NXP]  75.45 135.53 90 top
PQ30  PMPB20EN  [MX_SOT1220_NXP]  71.2 135.61 90 top
PQ31  NTR4502PT1G  [MX_SOT23_2D4_H51]  227.2 193.04 0 top
PQ33  LIN REG, 1085  [MX_TO252_LF3]  226.94 179.07 270 top
PQ34  BSC883N03LS  [MX_SO_8FL_COLAY]  232.16 208.61 0 top
PQ37  PMV33UPE  [MX_SOT23_2D4_H43]  237.87 209.12 90 top
PQ40  SIZ340DT-T1-GE3  [MX_POWERPAIR_8P_2PAD_VISHAY]  204.09 88.39 180 top
PQ46  RN47A4  [MX_SOT323_S5]  136.3 112.55 0 top
PQ54  PMV33UPE  [MX_SOT23_2D4_H43]  217.42 133.4 270 top
PQ56  BSC0906NS  [MX_SO_8FL_COLAY]  219.99 140.87 180 top
PQ60  SSM3K315T  [MX_SOT23_2D4_H44]  127.23 114.17 180 top
PQ80  2N7002  [MX_SOT23_H43_COLAY]  217.91 154.56 90 top
PQ115  PMBS3904  [MX_SOT23]  214.17 150.83 90 top
PQ591  NTMFS4925NT1G  [MX_SO_8FL_COLAY_9VI]  60.27 186.01 0 top
PQ592  BSC883N03LS  [MX_SO_8FL_COLAY_9VI]  62.99 178.26 0 top
PQ593  BSC883N03LS  [MX_SO_8FL_COLAY_9VI]  56.77 178.26 0 top
PQ594  NTMFS4925NT1G  [MX_SO_8FL_COLAY_9VI]  60.27 203.69 0 top
PQ595  BSC883N03LS  [MX_SO_8FL_COLAY_9VI]  62.99 195.92 0 top
PQ596  BSC883N03LS  [MX_SO_8FL_COLAY_9VI]  56.77 195.92 0 top
PQ601  NTMFS4925NT1G  [MX_SO_8FL_COLAY_9VI]  60.34 168.61 0 top
PQ602  BSC883N03LS  [MX_SO_8FL_COLAY_9VI]  56.76 160.76 0 top
PQ603  BSC883N03LS  [MX_SO_8FL_COLAY_9VI]  63.04 160.77 0 top
PQ604  NTMFS4925NT1G  [MX_SO_8FL_COLAY_9VI]  60.34 150.75 0 top
PQ605  BSC883N03LS  [MX_SO_8FL_COLAY_9VI]  56.76 143.01 0 top
PQ606  BSC883N03LS  [MX_SO_8FL_COLAY_9VI]  63.04 143.01 0 top
PQ611  BSC889N03LS  [MX_SO_8FL_COLAY_9VI]  118.85 222.81 0 top
PQ612  BSC883N03LS  [MX_SO_8FL_COLAY_9VI]  104.01 222.7 180 top
PQ613  BSC883N03LS  [MX_SO_8FL_COLAY_9VI]  110.21 222.7 180 top
PQ614  BSC889N03LS  [MX_SO_8FL_COLAY_9VI]  140.34 222.81 0 top
PQ615  BSC883N03LS  [MX_SO_8FL_COLAY_9VI]  131.57 222.7 180 top
PQ616  BSC883N03LS  [MX_SO_8FL_COLAY_9VI]  125.22 222.7 180 top
PQ651  BSC889N03LS  [MX_SO_8FL_COLAY_9VI]  216.66 202.8 0 top
PQ652  BSC889N03LS  [MX_SO_8FL_COLAY_9VI]  215.07 195.73 270 top
PQ653  BSC889N03LS  [MX_SO_8FL_COLAY_9VI]  215.07 189.38 270 top
PQ691  PMV33UPE  [MX_SOT23_2D4_H43]  227.97 160.91 180 top
PQ9777  2N7002  [MX_SOT23_H43]  206.38 51.69 0 top
PQ9779  PMBS3904  [MX_SOT23_H61]  204.06 44.09 90 top
PQ9784  AP2334GN-HF  [MX_SOT23_2D4_H55]  38.99 227.97 270 top
PQ9786  PMV33UPE  [MX_SOT23_2D4_H43]  52.58 128.42 0 top
PQ9787  2N7002  [MX_SOT23_H43]  138.61 13.12 0 top
PR2  330  [MX_R0805_SMALL_T02]  65.96 219.56 270 top
PR3  330  [MX_R0805_SMALL_T02]  119.48 113.79 90 top
PR4  330  [MX_R0805_SMALL_T02]  133.1 110.67 270 top
PR5  8.2K  [MX_R0402_SMALL_T01]  229.87 197.87 90 top
PR6  330  [MX_R0805_SMALL_T02]  230.5 202.92 180 top
PR7  330  [MX_R0805_SMALL_T02]  229.11 156.97 180 top
PR8  330  [MX_R0805_SMALL_T02]  217.47 215.8 180 top
PR9  330  [MX_R0805_SMALL_T02]  208.66 211.58 90 top
PR11  0  [MX_R0402_SMALL_T01]  216.03 227.71 270 top
PR12  150K  [MX_R0402_SMALL_T01]  217.42 228.09 0 top
PR14  1K  [MX_R0402_SMALL_T01]  208.74 105.79 90 top
PR115  10K  [MX_R0402_SMALL_T01]  137.16 92.2 180 top
PR121  100 Ohm  [MX_R0402_SMALL_T01]  239.57 215.85 90 top
PR122  1K  [MX_R0402_SMALL_T01]  231.01 214.38 0 top
PR123  2.2  [MX_R0603_SMALL_T01]  209.73 145.19 180 top
PR124  39.2K  [MX_R0402_SMALL_T01]  123.95 95.76 90 top
PR125  100K  [MX_R0402_SMALL_T01]  210.97 155.07 270 top
PR126  100K  [MX_R0402_SMALL_T01]  210.06 155.07 90 top
PR127  100  [MX_R0805_SMALL_T02]  128.88 100.43 180 top
PR128  24.9K  [MX_R0402_SMALL_T01]  130.91 97.66 270 top
PR129  4.7K  [MX_R0402_SMALL_T01]  130.78 100.33 90 top
PR130  0  [MX_R0402_SMALL_T01]  124.18 100.97 270 top
PR131  10  [MX_R1206]  119.38 100.2 270 top
PR132  1K  [MX_R0402_SMALL_T01]  124.21 99.31 270 top
PR133  4.87KOHM  [MX_R0402_SMALL_T01]  126.03 99.31 90 top
PR134  100 Ohm  [MX_R0402_SMALL_T01]  215.01 144.17 90 top
PR135  1K  [MX_R0402_SMALL_T01]  215.42 136.3 180 top
PR136  100K  [MX_R0402_SMALL_T01]  37.93 230.26 180 top
PR137  10K  [MX_R0402_SMALL_T01]  214.1 134.61 270 top
PR138  100K  [MX_R0402_SMALL_T01]  235.29 203.52 270 top
PR139  100K  [MX_R0402_SMALL_T01]  218.08 146.66 90 top
PR161  2.2  [MX_R0805_SMALL_T02]  194.77 94.03 0 top
PR162  10K  [MX_R0402_SMALL_T01]  189.43 92.38 0 top
PR163  0  [MX_R0805_SMALL_T02]  206.88 91.57 270 top
PR164  8.2K  [MX_R0402_SMALL_T01]  207.41 89.33 90 top
PR165  2.2  [MX_R0805_SMALL_T02]  196.6 88.65 180 top
PR166  4.7Ohm  [MX_R1206]  200.91 85.34 270 top
PR167  10K  [MX_R0402_SMALL_T01]  187.55 93.34 180 top
PR168  470K  [MX_R0402_SMALL_T01]  192.35 89.05 180 top
PR170  470K  [MX_R0402_SMALL_T01]  186.72 92.38 180 top
PR171  8.2K  [MX_R0402_SMALL_T01]  205.1 86.03 180 top
PR172  4.53K  [MX_R0402_SMALL_T01]  189.18 90.55 180 top
PR173  0  [MX_R0402_SMALL_T01]  189 88.72 180 top
PR174  121K  [MX_R0402_SMALL_T01]  189.43 93.29 0 top
PR175  10K  [MX_R0402_SMALL_T01]  190.73 88.72 0 top
PR187  8.2K  [MX_R0402_SMALL_T01]  228.09 164.49 0 top
PR188  8.2K  [MX_R0402_SMALL_T01]  229.06 189.13 180 top
PR189  8.2K  [MX_R0402_SMALL_T01]  229.36 188.21 180 top
PR191  10K  [MX_R0402_SMALL_T01]  227.71 188.21 180 top
PR192  200  [MX_R0402_SMALL_T01]  227.08 184.53 180 top
PR193  330  [MX_R0402_SMALL_T01]  228.35 185.04 90 top
PR194  0  [MX_R0402_SHORT_SMALL_T01]  227.08 185.45 0 top
PR195  8.2K  [MX_R0402_SMALL_T01]  239.57 214.2 90 top
PR196  0  [MX_R0402_SHORT_SMALL_T01]  232.36 216.28 180 top
PR198  10K  [MX_R0402_SMALL_T01]  238.81 212.55 180 top
PR199  8.2K  [MX_R0402_SMALL_T01]  229.34 214.38 0 top
PR234  10K  [MX_R0402_SMALL_T01]  55.35 123.98 270 top
PR235  1KOhm  [MX_R0402_SMALL_T01]  53.9 123.7 180 top
PR236  10  [MX_R0402_SMALL_T01]  55.32 120.02 90 top
PR244  100 Ohm  [MX_R0402_SMALL_T01]  127.56 117.16 270 top
PR245  100K  [MX_R0402_SMALL_T01]  126.29 116.76 180 top
PR248  0  [MX_R0402_SMALL_T01]  138.3 111.38 90 top
PR249  10  [MX_R0402_SMALL_T01]  134.95 109.52 90 top
PR302  8.2K  [MX_R0402_SMALL_T01]  214.45 141.48 0 top
PR305  8.2K  [MX_R0402_SMALL_T01]  215.42 137.21 0 top
PR312  16.9K  [MX_R0402_SMALL_T01]  126.95 99.31 90 top
PR313  0  [MX_R0402_SMALL_T01]  125.09 100.97 90 top
PR317  100  [MX_R0402_SMALL_T01]  63.83 125.48 90 top
PR340  0  [MX_R0805_SMALL_T02]  129.94 114 90 top
PR341  0  [MX_R0805_SMALL_T02]  49.73 127.3 90 top
PR381  1K  [MX_R0402_SMALL_T01]  215.67 153.87 90 top
PR432  10K  [MX_R0402_SMALL_T01]  219.25 157.58 270 top
PR511  10K  [MX_R0402_SMALL_T01]  227.57 149.76 90 top
PR512  10K  [MX_R0402_SMALL_T01]  209.04 223.34 180 top
PR601  8.2K  [MX_R0402_SMALL_T01]  64.83 165.48 90 top
PR602  2.2  [MX_R0603_SMALL_T01]  66.47 170.51 0 top
PR603  0 Ohm  [MX_R0805_SMALL_T02]  65.91 167.55 180 top
PR604  2.2Ohm  [MX_R1206_H26]  73.15 169.29 270 top
PR605  8.2K  [MX_R0402_SMALL_T01]  65.76 155.97 90 top
PR606  4.7  [MX_R1206]  68.66 155.57 180 top
PR608  8.2K  [MX_R0402_SMALL_T01]  64.8 147.68 90 top
PR609  2.2  [MX_R0603_SMALL_T01]  66.12 152.58 0 top
PR610  0 Ohm  [MX_R0805_SMALL_T02]  65.91 150.11 180 top
PR611  2.2Ohm  [MX_R1206_H26]  74.45 151.92 270 top
PR612  8.2K  [MX_R0402_SMALL_T01]  65.58 138.29 90 top
PR613  4.7  [MX_R1206]  68.58 139.01 180 top
PR621  100  [MX_R0402_SMALL_T01]  81.97 207.49 180 top
PR622  100  [MX_R0402_SMALL_T01]  83.67 207.52 0 top
PR623  100  [MX_R0402_SMALL_T01]  82.83 228.65 90 top
PR624  100  [MX_R0402_SMALL_T01]  84.96 227.97 0 top
PR641  0  [MX_R0805_SMALL_T02]  23.22 170.59 0 top
PR5801  787  [MX_R0402_SMALL_T01]  73.79 209.3 270 top
PR5802  3.09K  [MX_R0402_SMALL_T01]  75.56 210.06 0 top
PR5803  680  [MX_R0402_SMALL_T01]  76.38 211.46 270 top
PR5804  3.09K  [MX_R0402_SMALL_T01]  71.25 214.76 270 top
PR5805  680  [MX_R0402_SMALL_T01]  73.05 213.77 180 top
PR5806  10K  [MX_R0402_SMALL_T01]  79.1 208.53 270 top
PR5807  680  [MX_R0402_SMALL_T01]  75.7 225.3 90 top
PR5808  100K  [MX_R0402_SMALL_T01]  78.21 227.43 0 top
PR5809  10K  [MX_R0402_SMALL_T01]  79.02 205 270 top
PR5810  3.09K  [MX_R0402_SMALL_T01]  73.28 210.57 180 top
PR5811  680  [MX_R0402_SMALL_T01]  73.28 212.85 180 top
PR5812  100K  [MX_R0402_SMALL_T01]  73.15 220.73 180 top
PR5813  11.3K  [MX_R0402_SMALL_T01]  75.92 227.43 180 top
PR5814  3.09K  [MX_R0402_SMALL_T01]  77.72 209.98 180 top
PR5815  680  [MX_R0402_SMALL_T01]  77.29 211.46 270 top
PR5816  1K  [MX_R0402_SMALL_T01]  70.99 219.2 0 top
PR5817  45.3  [MX_R0402_SMALL_T01]  88.52 225.12 180 top
PR5818  100  [MX_R0402_SMALL_T01]  88.52 224.21 180 top
PR5819  10  [MX_R0402_SMALL_T01]  86.36 223.62 0 top
PR5820  49.9  [MX_R0402_SMALL_T01]  86.36 224.66 0 top
PR5821  0  [MX_R0402_SMALL_T01]  88.52 223.29 180 top
PR5822  75  [MX_R0402_SMALL_T01]  86.36 221.77 180 top
PR5823  51  [MX_R0402_SMALL_T01]  88.52 222.38 180 top
PR5824  15.8K  [MX_R0402_SMALL_T01]  84.02 209.78 90 top
PR5825  464  [MX_R0402_SMALL_T01]  86.97 212.14 90 top
PR5826  69.8K  [MX_R0402_SMALL_T01]  87.02 209.98 90 top
PR5827  6.34K  [MX_R0402_SMALL_T01]  86.06 212.14 90 top
PR5828  174K  [MX_R0402_SMALL_T01]  88.57 213.41 180 top
PR5829  0  [MX_R0402_SMALL_T01]  86.36 213.41 180 top
PR5830  3.32K  [MX_R0402_SMALL_T01]  88.57 214.33 180 top
PR5831  0  [MX_R0402_SMALL_T01]  86.36 214.33 180 top
PR5832  182K  [MX_R0402_SMALL_T01]  88.57 215.24 180 top
PR5833  1.78K  [MX_R0402_SMALL_T01]  86.36 215.24 180 top
PR5834  5.49K  [MX_R0402_SMALL_T01]  88.57 217.98 180 top
PR5835  200  [MX_R0402_SMALL_T01]  86.36 217.98 180 top
PR5836  64.9K  [MX_R0402_SMALL_T01]  84.96 209.78 90 top
PR5837  12K  [MX_R0402_SMALL_T01]  86.11 209.98 90 top
PR5838  3.65K  [MX_R0402_SMALL_T01]  86.36 217.07 180 top
PR5839  18.2K  [MX_R0402_SMALL_T01]  88.57 217.07 180 top
PR5840  18K  [MX_R0402_SMALL_T01]  88.57 216.15 180 top
PR5841  365  [MX_R0402_SMALL_T01]  86.36 216.15 180 top
PR5842  316  [MX_R0402_SMALL_T01]  84.96 212.22 90 top
PR5843  11.3K  [MX_R0402_SMALL_T01]  83.9 212.22 90 top
PR5844  0  [MX_R0402_SMALL_T01]  82.02 211.33 90 top
PR5845  10K  [MX_R0402_SMALL_T01]  80.92 209.42 90 top
PR5846  51  [MX_R0402_SMALL_T01]  80.01 211.58 270 top
PR5847  16.9K  [MX_R0402_SMALL_T01]  80.98 211.61 90 top
PR5848  0  [MX_R0402_SMALL_T01]  82.21 226.06 270 top
PR5849  9.76K  [MX_R0402_SMALL_T01]  80.26 226.31 90 top
PR5850  10K  [MX_R0402_SMALL_T01]  80.95 228.35 270 top
PR5851  28K  [MX_R0402_SMALL_T01]  81.18 226.31 270 top
PR5852  1  [MX_R0402_SMALL_T01]  70.99 218.19 180 top
PR5853  560K  [MX_R0402_SMALL_T01]  73.15 217.32 0 top
PR5854  1  [MX_R0402_SMALL_T01]  71.86 227.08 90 top
PR5855  510K  [MX_R0402_SMALL_T01]  73.71 225.32 270 top
PR5856  100K  [MX_R0402_SMALL_T01]  84.96 227.03 180 top
PR5857  1  [MX_R0402_SMALL_T01]  86.36 219.84 0 top
PR5858  0  [MX_R0402_SMALL_T01]  86.36 222.68 0 top
PR5859  0  [MX_R0402_SMALL_T01]  70.31 222.55 0 top
PR5860  10K  [MX_R0402_SMALL_T01]  69.67 223.55 0 top
PR5862  10.5K  [MX_R0402_SMALL_T01]  90.58 217.5 90 top
PR5863  18K  [MX_R0402_SMALL_T01]  91.49 217.5 90 top
PR5864  16.9K  [MX_R0402_SMALL_T01]  90.47 220.6 90 top
PR5865  11.5K  [MX_R0402_SMALL_T01]  91.39 220.6 90 top
PR5866  10  [MX_R0402_SMALL_T01]  86.36 220.85 180 top
PR5867  453  [MX_R0402_SMALL_T01]  86.36 218.9 180 top
PR5868  0 Ohm  [MX_R0402_SMALL_T01]  88.65 218.95 180 top
PR5869  11.3K  [MX_R0402_SMALL_T01]  88.52 221.44 180 top
PR5870  100K  [MX_R0402_SMALL_T01]  72.77 222.66 0 top
PR5871  432K  [MX_R0402_SMALL_T01]  73.18 216.2 0 top
PR5872  8.45K  [MX_R0402_SMALL_T01]  74.45 227.51 270 top
PR5873  432K  [MX_R0402_SMALL_T01]  74.78 225.3 270 top
PR5874  9.76K  [MX_R0402_SMALL_T01]  70.94 216.23 0 top
PR5875  348KOhm  [MX_R0402_SMALL_T01]  71.63 224.79 0 top
PR5876  2.2  [MX_R0805_SMALL_T02]  80.42 205.03 90 top
PR5877  680  [MX_R0402_SMALL_T01]  79.35 225.37 90 top
PR5878  0  [MX_R0402_SMALL_T01]  78.11 213.26 0 top
PR5879  0  [MX_R0402_SMALL_T01]  73.15 219.46 180 top
PR5880  787  [MX_R0402_SMALL_T01]  74.93 208.66 270 top
PR5881  787  [MX_R0402_SMALL_T01]  70.33 214.76 270 top
PR5882  787  [MX_R0402_SMALL_T01]  78.18 208.53 270 top
PR5883  604  [MX_R0402_SMALL_T01]  76.81 228.73 90 top
PR5884  604  [MX_R0402_SMALL_T01]  77.72 228.73 90 top
PR5901  2.2Ohm  [MX_R1206_H26]  73.53 187.07 270 top
PR5902  2.2  [MX_R0603_SMALL_T01]  68.12 187.2 0 top
PR5903  0 Ohm  [MX_R0805_SMALL_T02]  64.41 185.24 270 top
PR5904  8.2K  [MX_R0402_SMALL_T01]  64.77 182.96 90 top
PR5905  4.7  [MX_R1206]  68.58 173.15 180 top
PR5906  8.2K  [MX_R0402_SMALL_T01]  65.68 173.53 90 top
PR5908  8.2K  [MX_R0402_SMALL_T01]  64.74 200.53 90 top
PR5909  2.2  [MX_R0603_SMALL_T01]  64.85 208.81 270 top
PR5910  0 Ohm  [MX_R0805_SMALL_T02]  64.31 202.79 270 top
PR5911  2.2Ohm  [MX_R1206_H26]  69.6 204.09 270 top
PR5912  8.2K  [MX_R0402_SMALL_T01]  64.74 191.13 90 top
PR5913  4.7  [MX_R1206]  68.58 190.75 180 top
PR6101  8.2K  [MX_R0402_SMALL_T01]  120.14 217.5 0 top
PR6102  2.2  [MX_R0603_SMALL_T01]  91.54 229.54 270 top
PR6103  0 Ohm  [MX_R0805_SMALL_T02]  119.89 214.88 45 top
PR6104  2.2Ohm  [MX_R1206_H26]  95.5 230.25 0 top
PR6105  8.2K  [MX_R0402_SMALL_T01]  103.38 227.99 180 top
PR6106  4.7  [MX_R1206]  114.55 220.45 90 top
PR6108  8.2K  [MX_R0402_SMALL_T01]  141.6 217.53 0 top
PR6109  2.2  [MX_R0603_SMALL_T01]  144.63 227.43 0 top
PR6110  0 Ohm  [MX_R0805_SMALL_T02]  140.82 214.83 45 top
PR6111  2.2Ohm  [MX_R1206_H26]  151.99 229.34 270 top
PR6112  8.2K  [MX_R0402_SMALL_T01]  123.95 227.99 180 top
PR6113  4.7  [MX_R1206]  135.99 220.45 90 top
PR6506  10K  [MX_R0402_SMALL_T01]  214.5 224.41 270 top
PR6601  2.2  [MX_R0603_SMALL_T01]  118.62 49.66 180 top
PR6602  7.68K  [MX_R0402_SMALL_T01]  119.1 56.13 270 top
PR6603  2.1K  [MX_R0402_SMALL_T01]  120.28 51.1 90 top
PR6605  8.25kOHM  [MX_R0402_SMALL_T01]  120.26 52.8 270 top
PR6607  100K  [MX_R0402_SMALL_T01]  214.45 123.93 180 top
PR6608  162K  [MX_R0402_SMALL_T01]  213.23 129.49 180 top
PR6609  51K  [MX_R0402_SMALL_T01]  212.98 130.78 90 top
PR6610  1K  [MX_R0402_SMALL_T01]  214.1 126.19 90 top
PR6611  33KOHM  [MX_R0402_SMALL_T01]  214 130.78 90 top
PR6806  0  [MX_R0402_SMALL_T01]  44.93 226.01 180 top
PR6807  6.2K  [MX_R0402_SMALL_T01]  44.93 226.92 0 top
PR6809  10K  [MX_R0402_SMALL_T01]  46.46 227.89 0 top
PR6810  2.2  [MX_R0603_SMALL_T01]  42.04 238.25 270 top
PR70176  10K  [MX_R0402_SMALL_T01]  63.75 121.54 0 top
PR70188  0  [MX_R0402_SMALL_T01]  61.98 119.76 180 top
PR70189  0  [MX_R0402_SMALL_T01]  62.69 123.42 180 top
PR70190  17.8KOHM  [MX_R0402_SMALL_T01]  72.64 122.94 90 top
PR70193  0 Ohm  [MX_R0805_SMALL_T02]  70.92 127.48 90 top
PR70194  10KOhm  [MX_R0402_SMALL_T01]  64.39 120.14 90 top
PR70195  1K  [MX_R0603_SMALL_T01]  87.5 144.91 90 top
PR70196  30K  [MX_R0402_SMALL_T01]  61.98 118.24 0 top
PR70198  2.2  [MX_R0805_SMALL_T02]  72.64 119.13 180 top
PR70199  4.7  [MX_R1206]  69.67 132.99 180 top
PR70201  14.3K  [MX_R0402_SMALL_T01]  61.98 120.78 0 top
PR70202  2.2  [MX_R0603_SMALL_T01]  73.38 124.43 180 top
PR70203  0 Ohm  [MX_R0805_SMALL_T02]  74.55 122.94 0 top
PR70204  8.2K  [MX_R0402_SMALL_T01]  71.4 129.74 90 top
PR70205  1K  [MX_R0402_SMALL_T01]  65.66 125.48 270 top
PR70206  10K  [MX_R0402_SMALL_T01]  67.69 125.48 90 top
PR70207  0  [MX_R0402_SHORT_SMALL_T01]  63.37 120.14 90 top
PR70210  0 Ohm  [MX_R0805_SMALL_T02]  220.65 200.3 270 top
PR70211  10K  [MX_R0402_SMALL_T01]  212.09 225.58 0 top
PR70212  1K  [MX_R0603_SMALL_T01]  210.95 167.61 270 top
PR70213  24.9K  [MX_R0402_SMALL_T01]  212.15 227.69 180 top
PR70215  2.2 Ohm  [MX_R0805_SMALL_T02]  211.71 216.53 90 top
PR70216  4.7  [MX_R1206]  211.13 200.12 180 top
PR70217  15K  [MX_R0402_SMALL_T01]  210.82 226.06 270 top
PR70219  2.2  [MX_R0603_SMALL_T01]  216.95 219.61 180 top
PR70220  0  [MX_R0805_SMALL_T02]  214.76 215.67 270 top
PR70221  8.2K  [MX_R0402_SMALL_T01]  219.68 197.38 180 top
PR70222  1KOhm  [MX_R0402_SMALL_T01]  217.3 224.82 180 top
PR70223  10K  [MX_R0402_SMALL_T01]  217.04 226.19 90 top
PR70224  0  [MX_R0603_SHORT_SMALL_T01]  212.39 226.62 0 top
PR70225  0  [MX_R0402_SMALL_T01]  210.82 227.97 90 top
PR70227  21K  [MX_R0402_SMALL_T01]  214.76 217.6 0 top
PR70228  0  [MX_R0402_SMALL_T01]  62.69 122.5 180 top
PR70231  0  [MX_R0402_SMALL_T01]  87.88 226.44 180 top
PR70238  0  [MX_R0402_SMALL_T01]  123.95 92.33 270 top
PR70244  330  [MX_R0805_SMALL_T02]  224.54 160.91 180 top
PR70245  330  [MX_R0805_SMALL_T02]  224.54 159.13 180 top
PR70246  330  [MX_R0805_SMALL_T02]  197.1 66.47 180 top
PR70249  0  [MX_R0402_SHORT_SMALL_T01]  216.03 142.9 180 top
PR70250  8.2K  [MX_R0402_SMALL_T01]  216.41 144.27 270 top
PR70254  8.2K  [MX_R0402_SMALL_T01]  40.64 230.89 270 top
PR70256  8.2K  [MX_R0402_SMALL_T01]  54.08 124.61 180 top
PR70260  0  [MX_R0402_SMALL_T01]  217.96 226.19 90 top
PR70261  0  [MX_R0402_SMALL_T01]  64.74 125.48 270 top
PR70291  0  [MX_R0805_SMALL_T02]  206.17 83.72 180 top
PR70296  330  [MX_R0805_SMALL_T02]  228.6 196.09 0 top
PR70298  0  [MX_R0402_SMALL_T01]  45.24 237.06 270 top
PRT581  100K  [MX_R0402_SMALL_T01]  75.18 183.51 0 top
PRT582  100K  [MX_R0402_SMALL_T01]  100.41 216.18 90 top
PRT583  100K  [MX_R0402_SMALL_T01]  63.83 188.75 270 top
PRT584  100K  [MX_R0402_SMALL_T01]  101.47 228.09 90 top
PT1  TPC26T  [MX_TPC26T_S4_68]  232.92 203.33 180 bottom
PT2  TPC26T  [MX_TPC26T_S4_68]  233.07 207.16 180 bottom
PT3  TPC26T  [MX_TPC26T_S4_68]  232.99 205.36 180 bottom
PT4  TPC26T  [MX_TPC26T_S4_68]  45.47 223.06 180 bottom
PT5  TPC26T  [MX_TPC26T_S4_68]  45.85 228.75 180 bottom
PT6  TPC26T  [MX_TPC26T_S4_68]  232.28 143 180 bottom
PT7  TPC26T  [MX_TPC26T_S4_68]  232.28 141.05 180 bottom
PT8  TPC26T  [MX_TPC26T_S4_68]  232.28 144.88 180 bottom
PT9  TPC26T  [MX_TPC26T_S4_68]  221.84 145.19 180 bottom
PT10  TPC26T  [MX_TPC26T_S4_68]  231.95 211.4 180 bottom
PT11  TPC26T  [MX_TPC26T_S4_68]  238.38 207.24 180 bottom
PT12  TPC26T  [MX_TPC26T_S4_68]  238.38 209.07 180 bottom
PT13  TPC26T  [MX_TPC26T_S4_68]  224 193.45 180 bottom
PT14  TPC26T  [MX_TPC26T_S4_68]  222.5 173.92 180 bottom
PT15  TPC26T  [MX_TPC26T_S4_68]  238.12 205.36 180 bottom
PT21  TPC26T  [MX_TPC26T_S4_68]  157.57 20.09 45 bottom
PT22  TPC26T  [MX_TPC26T_S4_68]  183.01 32.35 180 bottom
PT23  TPC26T  [MX_TPC26T_S4_68]  132.41 14.02 180 bottom
PT24  TPC26T  [MX_TPC26T_S4_68]  186.11 33.27 180 bottom
PT25  TPC26T  [MX_TPC26T_S4_68]  188.01 33.27 180 bottom
PT26  TPC26T  [MX_TPC26T_S4_68]  209.1 191.28 180 bottom
PT27  TPC26T  [MX_TPC26T_S4_68]  209.22 205.19 180 bottom
PT28  TPC26T  [MX_TPC26T_S4_68]  208.91 201.8 180 bottom
PT29  TPC26T  [MX_TPC26T_S4_68]  208.89 194.68 180 bottom
PT30  TPC26T  [MX_TPC26T_S4_68]  209.5 187.86 180 bottom
PT31  TPC26T  [MX_TPC26T_S4_68]  58.78 155.3 180 bottom
PT32  TPC26T  [MX_TPC26T_S4_68]  59.23 138.18 180 bottom
PT33  TPC26T  [MX_TPC26T_S4_68]  65.3 190.4 180 bottom
PT34  TPC26T  [MX_TPC26T_S4_68]  56.31 192.48 180 bottom
PT35  TPC26T  [MX_TPC26T_S4_68]  64.36 139.52 180 bottom
PT36  TPC26T  [MX_TPC26T_S4_68]  65.66 137.24 180 bottom
PT37  TPC26T  [MX_TPC26T_S4_68]  62.36 174.88 180 bottom
PT38  TPC26T  [MX_TPC26T_S4_68]  65.46 172.67 180 bottom
PT39  TPC26T  [MX_TPC26T_S4_68]  59.94 173.1 180 bottom
PT40  TPC26T  [MX_TPC26T_S4_68]  64.21 154.99 180 bottom
PT41  TPC26T  [MX_TPC26T_S4_68]  83.95 152.91 180 bottom
PT42  TPC26T  [MX_TPC26T_S4_68]  84.33 169.54 180 bottom
PT43  TPC26T  [MX_TPC26T_S4_68]  85.72 165.48 180 bottom
PT44  TPC26T  [MX_TPC26T_S4_68]  86.49 169.42 180 bottom
PT45  TPC26T  [MX_TPC26T_S4_68]  86.36 171.7 180 bottom
PT46  TPC26T  [MX_TPC26T_S4_68]  87.22 177.42 180 bottom
PT47  TPC26T  [MX_TPC26T_S4_68]  86.23 151.89 180 bottom
PT48  TPC26T  [MX_TPC26T_S4_68]  89.15 152.65 180 bottom
PT49  TPC26T  [MX_TPC26T_S4_68]  86.54 161.39 180 bottom
PT50  TPC26T  [MX_TPC26T_S4_68]  82.17 147.7 180 bottom
PT51  TPC26T  [MX_TPC26T_S4_68]  60.27 219.41 180 bottom
PT52  TPC26T  [MX_TPC26T_S4_68]  51.92 205.21 180 bottom
PT53  TPC26T  [MX_TPC26T_S4_68]  53.04 157.07 180 bottom
PT54  TPC26T  [MX_TPC26T_S4_68]  50.16 183.08 180 bottom
PT55  TPC26T  [MX_TPC26T_S4_68]  51.66 151.31 180 bottom
PT56  TPC26T  [MX_TPC26T_S4_68]  54.25 136.35 180 bottom
PT57  TPC26T  [MX_TPC26T_S4_68]  50.39 161.95 180 bottom
PT58  TPC26T  [MX_TPC26T_S4_68]  51.21 141.22 180 bottom
PT59  TPC26T  [MX_TPC26T_S4_68]  49.73 168.43 180 bottom
PT60  TPC26T  [MX_TPC26T_S4_68]  50.27 191.57 180 bottom
PT265  TPC26T  [MX_TPC26T_S4_68]  62.41 93.37 180 bottom
PT266  TPC26T  [MX_TPC26T_S4_68]  68.38 95.12 180 bottom
PT267  TPC26T  [MX_TPC26T_S4_68]  66.4 94.89 180 bottom
PT268  TPC26T  [MX_TPC26T_S4_68]  63.91 94.69 180 bottom
PT269  TPC26T  [MX_TPC26T_S4_68]  69.65 96.57 180 bottom
PT270  TPC26T  [MX_TPC26T_S4_68]  67.01 96.82 180 bottom
PT271  TPC26T  [MX_TPC26T_S4_68]  62.71 96.65 180 bottom
PT272  TPC26T  [MX_TPC26T_S4_68]  61.77 95.02 180 bottom
PT273  TPC26T  [MX_TPC26T_S4_68]  60.88 96.55 180 bottom
PT274  TPC26T  [MX_TPC26T_S4_68]  64.64 96.57 180 bottom
PU5  APL5611CI-TRG  [MX_SOT23_S6_FITI]  126.75 96.57 270 top
PU7  RT8068AZQW  [MX_DFN_10P_20_S118_PAD_R_4V]  211.84 125.48 0 top
PU9  RT8237EZQW  [MX_DFN_10P_20_S118_PAD_R_4V]  192.61 91.34 270 top
PU10  RT8125CGQW  [MX_DFN_10P_20_S118_PAD_R_4V]  69.22 121.67 90 top
PU12  RT9406GV8  [MX_SOIC_8P_26_118X110_MAXIM]  117.91 52.63 0 top
